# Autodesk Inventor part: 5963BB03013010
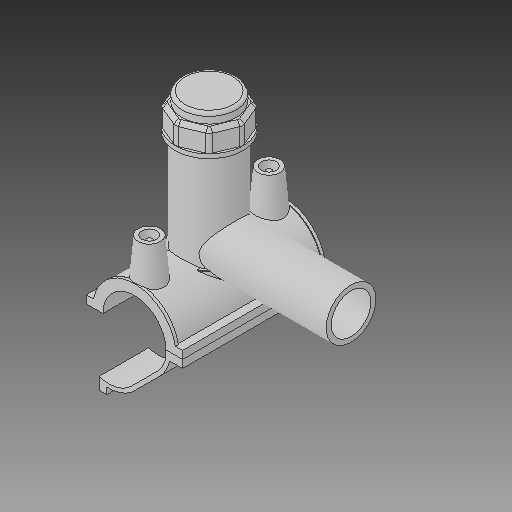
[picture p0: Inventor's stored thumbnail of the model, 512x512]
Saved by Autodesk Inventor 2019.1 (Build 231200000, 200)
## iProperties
Created: 2017-07
Part Number: 5963BB03013010
Material: Generic
Description: PLASSON TAPPING SADDLE 1 1/4''IPS x 1''IPS
Document SubType Name: Modeling
Designer: KIM
Mass: 1712.7 g
Surface Area: 2671.49 cm^2
Volume: 1712.7 cm^3
Density: 1 g/cm^3
Appearance: Default
Author: KIM
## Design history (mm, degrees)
derived "5963B.ipt"
feature "Solid1::5963B.ipt"
feature "Solid2::5963B.ipt"
feature "Solid4::5963B.ipt"
feature "Solid5::5963B.ipt"
tag "TaggingFeature1"
body "Solid1"
body "Solid2"
other parameters: "d_" = 42.1, "B_" = 64.516, "L_" = 100.076, "d_t" = 6, "H_2" = 93.726, "H_1" = 11.938, "d_1" = 33.3, "H_" = 94.996, "d1" = 54.73, "d148" = 0.6315, "d160" = 0.6315, "d169" = 3.2805, "d192" = 6.1236, "d0" = 42.1, "d2" = 64.516, "d3" = 10.525, "d4" = 100.076, "d5" = 0, "d6" = 0.1, "d8" = 0, "d19" = 6, "d20" = 6, "d21" = 60.0456, "d23" = 0, "d24" = 30.0228, "d26" = 0, "d29" = 3, "d30" = 14.03333, "d31" = 6, "d32" = 0, "d33" = 0, "d34" = 0.6, "d40" = 28.4596, "d41" = 37.89, "d43" = 0, "d45" = 0, "d47" = 87.4106, "d70" = 15, "d72" = 0, "d73" = 6, "d75" = 5, "d76" = 0, "d77" = 2.105, "d78" = 51.05, "d79" = 15, "d80" = 40.0304, "d82" = 5 deg, "d84" = 4, "d85" = 14, "d86" = 0, "d87" = 3, "d88" = 0, "d89" = 1, "d90" = 1, "d91" = 80.0608, "d92" = 0, "d93" = 0.5, "d94" = 22.15789, "d96" = 55.8246, "d97" = 2.00152, "d98" = 0, "d102" = 0.421, "d120" = 140 deg, "d121" = 24.228, "d122" = 20 deg, "d123" = 109.46, "d124" = 32.838, "d126" = 0, "d143" = 43.363, "d145" = 9.71538, "d149" = 0.6315, "d150" = 10.68692, "d153" = 100.076, "d154" = 0, "d156" = 27.365, "d157" = 160 deg, "d159" = 2.526, "d161" = 0.6315, "d162" = 60.0456, "d163" = 0, "d164" = 21.05, "d167" = 4.21, "d168" = 26.69756, "d170" = 3.2805, "d172" = 0, "d173" = 1, "d175" = 21.05, "d176" = 20 deg, "d177" = 2.947, "d178" = 12.63, "d180" = 0, "d183" = 5.052, "d184" = 2.3576, "d185" = 32.5247, "d186" = 32.5247, "d187" = 27.365, "d188" = 3.789, "d189" = 2.947, "d190" = 0, "d191" = 41.0475, "d193" = 6.1236, "d194" = 3.50266, "d195" = 90 deg, "d197" = 0, "d199" = 0, "d200" = 6.315, "d202" = 0, "d203" = 93.726, "d204" = 43.1946, "d205" = 31.8276, "d206" = 38.6478, "d207" = 70.2945, "d208" = 73.10628, "d209" = 87.16518, "d210" = 39.10248, "d211" = 45.468, "d212" = 36.3744, "d213" = -4.2408, "d216" = 0, "d217" = 4.21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
